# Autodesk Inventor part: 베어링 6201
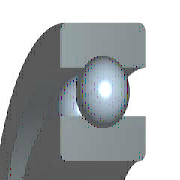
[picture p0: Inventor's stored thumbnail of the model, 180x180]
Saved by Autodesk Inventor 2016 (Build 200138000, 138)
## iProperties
IsCustomPart: 1
Created: 2012-02
Part Number: 베어링 6201
Material: 강철, 연강
Description: 깊은 그루브 볼 베어링
Document SubType Name: Modeling
Standard: KS B 2023
Designer: test
Standards Organization: KS
Language: ko-KR
Size Designation: 6201 - 12 x 32 x 10
Categories: <MemberInstance><Categories><Category DisplayName="샤프트 부품" InternalName="7f7aeb1f-a693-4053-b835-cee3144e0d98" Mnemonic="SHFT"><Category DisplayName="베어링" Inter
Density: 1 g/cm^3
Appearance: 노란색
Author: test
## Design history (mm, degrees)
sketch "스케치" dims "d0" = 5.2 (= -0.26 x WD + 0.26 x BD)
  geometry: L1 (2.4, 11)-(7.6, 11); L2 (5, 11)-(5, 8.4); L3 (5, 11)-(5, 13.6); L4 (3.068, 9.26)-(0, 9.26); L5 (0, 6)-(10, 6); L6 (3.068, 12.74)-(0, 12.74); L7 (0, 16)-(10, 16); L8 (10, 6)-(10, 9.26); L9 (6.932, 9.26)-(10, 9.26); L10 (6.932, 12.74)-(10, 12.74); L11 (10, 16)-(10, 12.74); L12 (-1.4, 0)-(8.4, 0) reference; L13 (0, -0.3)-(0, 5.3) reference
  constraints: 22 end point, 4 point on line, 2 collinear, 2 perpendicular, 2 symmetric about line, 1 midpoint, 1 parallel, 14 other
  dimensions: "d9" = 12 diameter of L5 L12 (= WD); "d11" = 32 diameter of L7 L12 (= BD); "d12" = 10 distance between parallel lines of L8 L13 (= KB); "d13" = 18.52 diameter of L9 L12 (= 0.326 x BD + 0.674 x WD)
revolve "본체" stored, may be unused: angle "d6" = 90 deg
revolve "볼" stored, may be unused: angle "d7" = 90 deg
pattern_circular "IDS_ARRAYBALL[SIMPL:T]" dims angle "d3" = 360 deg
body "Solid1"
fillet "모깎기1" dims "d1" = 0.6 (= KRS)
other parameters: "WD" = 12 [user parameter; used in 5 equation terms], "BD" = 32 [user parameter; used in 5 equation terms], "KB" = 10 [user parameter; used in 1 equation term], "KRS" = 0.6 [user parameter; used in 1 equation term], "d4" = 0, "d5" = 0, "d8" = 0, "d14" = 0, "d15" = 0, "BBA" = 0 [user parameter], "BC0" = 3100000 [user parameter], "BC" = 6890000 [user parameter], "BR" = 16 (= 0.5 x BD) [user parameter], "WR" = 6 (= 0.5 x WD) [user parameter]
